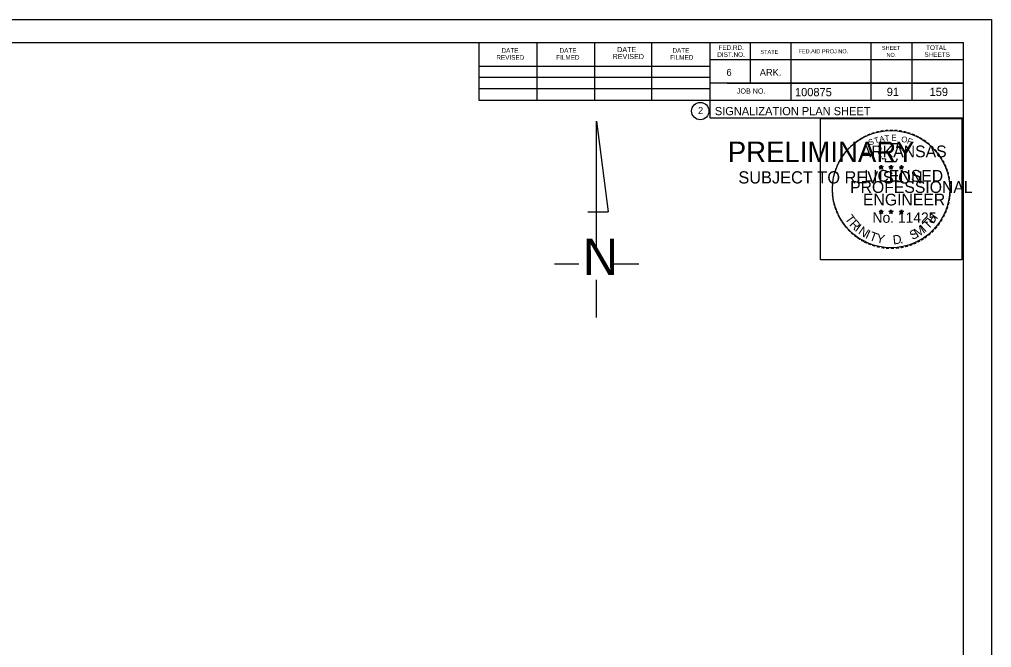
# Model space of a CAD drawing. Extents: x 1709451 to 1710451, y 561684 to 562324.
# Drawn here: x 1709955.8 to 1710451, y 562004 to 562324 of the extents above; entities that cross this region are included whole.
import ezdxf

# ---------------------------------------------------------------- set-up
doc = ezdxf.new("R2010")
doc.units = 0
for name, color, linetype in [('R_Alt Surface', 7, 'Continuous'), ('R_Alt Surface Annot', 7, 'Continuous'), ('R_Axis', 7, 'Continuous'), ('R_Axis Annot', 7, 'Continuous'), ('R_Detour Annot', 7, 'Continuous')]:
    doc.layers.add(name, color=color, linetype=linetype)

msp = doc.modelspace()

# ---------------------------------------------------------------- linework, layer by layer
at = {"layer": 'R_Alt Surface'}
for p, q in [((1709488.22, 562312.31), (1710436.76, 562312.31)), ((1710189.98, 562282.67), (1710189.98, 562312.31)), ((1710307.46, 562312.31), (1710307.46, 562273.91)), ((1710327.98, 562312.31), (1710327.98, 562291.49)), ((1710348.8, 562312.31), (1710348.8, 562282.67)), ((1710389.54, 562312.31), (1710389.54, 562282.67)), ((1710410.36, 562312.31), (1710410.36, 562282.67)), ((1710436.76, 561695.93), (1710436.76, 562312.31)), ((1710219.56, 562282.67), (1710219.56, 562311.71)), ((1710248.84, 562282.67), (1710248.84, 562311.71)), ((1710277.88, 562282.67), (1710277.88, 562311.71)), ((1710436.76, 562303.49), (1710307.46, 562303.49)), ((1710436.76, 562303.55), (1710436.76, 562303.55)), ((1710189.98, 562300.25), (1710307.46, 562300.25)), ((1710189.98, 562294.67), (1710307.46, 562294.67)), ((1710189.98, 562282.67), (1710189.98, 562288.85)), ((1710189.98, 562288.85), (1710307.46, 562288.85)), ((1710436.76, 562291.49), (1710307.46, 562291.49)), ((1710316.34, 562291.49), (1710436.76, 562291.49)), ((1710436.76, 562282.67), (1710189.98, 562282.67)), ((1710307.46, 562273.91), (1710436.76, 562273.91))]:
    msp.add_line(p, q, dxfattribs=at)
msp.add_circle((1710302.62, 562277.32), 4.4, dxfattribs=at)
at = {"layer": 'R_Alt Surface Annot'}
for p, q in [((1709451.02, 562324), (1710451.02, 562324)), ((1710363.59, 562204.86), (1710363.59, 562204.86))]:
    msp.add_line(p, q, dxfattribs=at)
for points in [[(1709451, 562324), (1710451.02, 562324), (1710451.02, 561683.98), (1709451, 561683.98)], [(1710363.83, 562273.55), (1710435.83, 562273.55), (1710435.83, 562201.55), (1710363.83, 562201.55)]]:
    msp.add_lwpolyline(points, close=True, dxfattribs=at)
msp.add_circle((1710399.83, 562237.55), 29.86, dxfattribs=at)
at = {"layer": 'R_Axis Annot'}
for p, q in [((1710393.74, 562249), (1710394.79, 562248.66)), ((1710393.74, 562249), (1710394.5, 562248.86)), ((1710393.74, 562249), (1710394.46, 562248.63)), ((1710394.14, 562247.77), (1710394.79, 562248.66)), ((1710394.14, 562247.77), (1710394.52, 562248.5)), ((1710394.14, 562247.77), (1710394.79, 562248.42)), ((1710394.79, 562249.76), (1710394.67, 562249)), ((1710394.79, 562248.66), (1710394.79, 562249.76)), ((1710394.79, 562249.76), (1710394.94, 562249.01)), ((1710395.83, 562249), (1710394.79, 562248.66)), ((1710395.43, 562247.77), (1710394.79, 562248.66)), ((1710395.43, 562247.77), (1710394.79, 562248.41)), ((1710395.83, 562249), (1710394.97, 562248.85)), ((1710395.43, 562247.77), (1710395.02, 562248.64)), ((1710395.83, 562249), (1710395.22, 562248.69)), ((1710398.75, 562249), (1710399.8, 562248.66)), ((1710398.75, 562249), (1710399.51, 562248.86)), ((1710398.75, 562249), (1710399.47, 562248.63)), ((1710399.15, 562247.77), (1710399.8, 562248.66)), ((1710399.15, 562247.77), (1710399.53, 562248.5)), ((1710399.15, 562247.77), (1710399.8, 562248.42)), ((1710399.8, 562249.76), (1710399.68, 562249)), ((1710399.8, 562248.66), (1710399.8, 562249.76)), ((1710399.8, 562249.76), (1710399.95, 562249.01)), ((1710400.84, 562249), (1710399.8, 562248.66)), ((1710400.44, 562247.77), (1710399.8, 562248.66)), ((1710400.44, 562247.77), (1710399.8, 562248.41)), ((1710400.84, 562249), (1710399.98, 562248.85)), ((1710400.44, 562247.77), (1710400.03, 562248.64)), ((1710400.84, 562249), (1710400.23, 562248.69)), ((1710404.05, 562248.96), (1710405.09, 562248.63)), ((1710404.05, 562248.96), (1710404.81, 562248.82)), ((1710404.05, 562248.96), (1710404.76, 562248.59)), ((1710404.45, 562247.74), (1710405.09, 562248.63)), ((1710404.45, 562247.74), (1710404.82, 562248.47)), ((1710404.45, 562247.74), (1710405.09, 562248.39)), ((1710405.09, 562249.72), (1710404.97, 562248.97)), ((1710405.09, 562248.63), (1710405.09, 562249.72)), ((1710405.09, 562249.72), (1710405.24, 562248.97)), ((1710406.13, 562248.96), (1710405.09, 562248.63)), ((1710405.73, 562247.74), (1710405.09, 562248.63)), ((1710405.73, 562247.74), (1710405.09, 562248.38)), ((1710406.13, 562248.96), (1710405.28, 562248.81)), ((1710405.73, 562247.74), (1710405.32, 562248.61)), ((1710406.13, 562248.96), (1710405.52, 562248.65)), ((1710393.73, 562226.28), (1710394.78, 562225.94)), ((1710393.73, 562226.28), (1710394.49, 562226.14)), ((1710393.73, 562226.28), (1710394.44, 562225.91)), ((1710394.13, 562225.05), (1710394.78, 562225.94)), ((1710394.13, 562225.05), (1710394.51, 562225.78)), ((1710394.13, 562225.05), (1710394.77, 562225.7)), ((1710394.78, 562227.04), (1710394.66, 562226.28)), ((1710395.42, 562225.05), (1710394.77, 562225.69)), ((1710394.78, 562225.94), (1710394.78, 562227.04)), ((1710394.78, 562227.04), (1710394.93, 562226.29)), ((1710395.82, 562226.28), (1710394.78, 562225.94)), ((1710395.42, 562225.05), (1710394.78, 562225.94)), ((1710395.82, 562226.28), (1710394.96, 562226.13)), ((1710395.42, 562225.05), (1710395.01, 562225.93)), ((1710395.82, 562226.28), (1710395.21, 562225.97)), ((1710398.74, 562226.28), (1710399.79, 562225.94)), ((1710398.74, 562226.28), (1710399.5, 562226.14)), ((1710398.74, 562226.28), (1710399.45, 562225.91)), ((1710399.14, 562225.05), (1710399.79, 562225.94)), ((1710399.14, 562225.05), (1710399.52, 562225.78)), ((1710399.14, 562225.05), (1710399.78, 562225.7)), ((1710399.79, 562227.04), (1710399.66, 562226.28)), ((1710400.43, 562225.05), (1710399.78, 562225.69)), ((1710399.79, 562225.94), (1710399.79, 562227.04)), ((1710399.79, 562227.04), (1710399.93, 562226.29)), ((1710400.83, 562226.28), (1710399.79, 562225.94)), ((1710400.43, 562225.05), (1710399.79, 562225.94)), ((1710400.83, 562226.28), (1710399.97, 562226.13)), ((1710400.43, 562225.05), (1710400.01, 562225.93)), ((1710400.83, 562226.28), (1710400.22, 562225.97)), ((1710404.04, 562226.25), (1710405.09, 562225.91)), ((1710404.04, 562226.25), (1710404.8, 562226.11)), ((1710404.04, 562226.25), (1710404.75, 562225.88)), ((1710404.44, 562225.02), (1710405.09, 562225.91)), ((1710404.44, 562225.02), (1710404.82, 562225.75)), ((1710404.44, 562225.02), (1710405.08, 562225.67)), ((1710405.09, 562227.01), (1710404.96, 562226.25)), ((1710405.73, 562225.02), (1710405.08, 562225.66)), ((1710405.09, 562225.91), (1710405.09, 562227.01)), ((1710405.09, 562227.01), (1710405.23, 562226.26)), ((1710406.13, 562226.25), (1710405.09, 562225.91)), ((1710405.73, 562225.02), (1710405.09, 562225.91)), ((1710406.13, 562226.25), (1710405.27, 562226.1)), ((1710405.73, 562225.02), (1710405.32, 562225.9)), ((1710406.13, 562226.25), (1710405.52, 562225.94))]:
    msp.add_line(p, q, dxfattribs=at)
for points in [[(1710393.87, 562260.63), (1710394.67, 562258.15)], [(1710404.4, 562257.86), (1710404.83, 562258.72), (1710402.77, 562258.64), (1710403.22, 562260.63), (1710393.87, 562260.63)], [(1710395.34, 562253.36), (1710395.34, 562253.1), (1710397.03, 562253.04), (1710396.87, 562251.62), (1710402.48, 562251.62), (1710403.08, 562253.23)], [(1710394.79, 562249.76), (1710395.43, 562247.77), (1710393.74, 562249), (1710395.83, 562249), (1710394.14, 562247.77), (1710394.79, 562249.76)], [(1710399.8, 562249.76), (1710400.44, 562247.77), (1710398.75, 562249), (1710400.84, 562249), (1710399.15, 562247.77), (1710399.8, 562249.76)], [(1710405.09, 562249.72), (1710405.73, 562247.74), (1710404.05, 562248.96), (1710406.13, 562248.96), (1710404.45, 562247.74), (1710405.09, 562249.72)], [(1710394.78, 562227.04), (1710395.42, 562225.05), (1710393.73, 562226.28), (1710395.82, 562226.28), (1710394.13, 562225.05), (1710394.78, 562227.04)], [(1710399.79, 562227.04), (1710400.43, 562225.05), (1710398.74, 562226.28), (1710400.83, 562226.28), (1710399.14, 562225.05), (1710399.79, 562227.04)], [(1710405.09, 562227.01), (1710405.73, 562225.02), (1710404.04, 562226.25), (1710406.13, 562226.25), (1710404.44, 562225.02), (1710405.09, 562227.01)]]:
    msp.add_lwpolyline(points, dxfattribs=at)
for centre, radius in [((1710394.79, 562248.66), 0.517), ((1710394.79, 562248.66), 0.434), ((1710394.79, 562248.66), 0.347), ((1710394.79, 562248.66), 0.297), ((1710394.79, 562248.66), 0.224), ((1710394.79, 562248.66), 0.149), ((1710394.79, 562248.66), 0.0889), ((1710399.8, 562248.66), 0.517), ((1710399.8, 562248.66), 0.434), ((1710399.8, 562248.66), 0.347), ((1710399.8, 562248.66), 0.297), ((1710399.8, 562248.66), 0.224), ((1710399.8, 562248.66), 0.149), ((1710399.8, 562248.66), 0.0889), ((1710405.09, 562248.62), 0.517), ((1710405.09, 562248.62), 0.434), ((1710405.09, 562248.62), 0.347), ((1710405.09, 562248.62), 0.297), ((1710405.09, 562248.62), 0.224), ((1710405.09, 562248.62), 0.149), ((1710405.09, 562248.62), 0.0889), ((1710394.78, 562225.94), 0.517), ((1710394.78, 562225.94), 0.434), ((1710394.78, 562225.94), 0.347), ((1710394.78, 562225.94), 0.297), ((1710394.78, 562225.94), 0.224), ((1710394.78, 562225.94), 0.149), ((1710394.78, 562225.94), 0.0889), ((1710399.78, 562225.94), 0.517), ((1710399.78, 562225.94), 0.434), ((1710399.78, 562225.94), 0.347), ((1710399.78, 562225.94), 0.297), ((1710399.78, 562225.94), 0.224), ((1710399.78, 562225.94), 0.149), ((1710399.78, 562225.94), 0.0889), ((1710405.08, 562225.91), 0.517), ((1710405.08, 562225.91), 0.434), ((1710405.08, 562225.91), 0.347), ((1710405.08, 562225.91), 0.297), ((1710405.08, 562225.91), 0.224), ((1710405.08, 562225.91), 0.149), ((1710405.08, 562225.91), 0.0889)]:
    msp.add_circle(centre, radius, dxfattribs=at)
at = {"layer": 'R_Detour Annot'}
for p, q in [((1710249.84, 562272.23), (1710255.62, 562226.03)), ((1710249.84, 562207.15), (1710249.84, 562272.23)), ((1710245.33, 562226.03), (1710255.62, 562226.03)), ((1710228.44, 562199.48), (1710240.78, 562199.48)), ((1710258.06, 562199.48), (1710271.25, 562199.48)), ((1710249.84, 562172.23), (1710249.84, 562191.37))]:
    msp.add_line(p, q, dxfattribs=at)

# ---------------------------------------------------------------- texts
at = {"layer": 'R_Alt Surface'}
for s, height, p in [('DATE', 2.346, (1710201.38, 562307.03)), ('DATE', 2.346, (1710230.96, 562307.03)), ('DATE', 2.638, (1710260.3, 562307.33)), ('DATE', 2.346, (1710288.44, 562307.03)), ('FED.RD.', 2.346, (1710311.9, 562308.47)), ('STATE', 2.052, (1710333.26, 562306.43)), ('FED.AID PROJ.NO.', 2.052, (1710352.64, 562306.73)), ('SHEET', 2.052, (1710395.12, 562308.47)), ('TOTAL', 2.346, (1710417.68, 562308.47)), ('REVISED', 2.346, (1710198.74, 562303.49)), ('FILMED', 2.346, (1710229.22, 562303.49)), ('REVISED', 2.638, (1710257.96, 562303.79)), ('FILMED', 2.346, (1710287.24, 562303.49)), ('DIST.NO.', 2.346, (1710311.3, 562304.93)), ('NO.', 2.052, (1710397.46, 562304.93)), ('SHEETS', 2.346, (1710416.84, 562304.93)), ('6', 3.52, (1710315.98, 562295.27)), ('ARK.', 3.517, (1710332.96, 562295.27)), ('JOB NO.', 2.638, (1710321.26, 562286.21)), ('100875', 4.2, (1710350.89, 562284.89)), ('91', 4.2, (1710397.62, 562284.99)), ('159', 4.2, (1710419.46, 562284.99)), ('2', 3.52, (1710301.47, 562275.86)), ('SIGNALIZATION PLAN SHEET', 4.2, (1710310.05, 562275.2))]:
    msp.add_text(s, height=height, dxfattribs=at).set_placement(p)
at = {"layer": 'R_Axis'}
for s, height, p in [('PRELIMINARY', 10.5, (1710316.62, 562251.3)), ('SUBJECT TO REVISION', 6.2253, (1710322.04, 562240.42))]:
    msp.add_text(s, height=height, dxfattribs=at).set_placement(p)
at = {"layer": 'R_Axis Annot'}
for s, height, rotation, p in [('-', 4.8, 5.8968, (1710396.58, 562265.55)), ('-', 4.8, 0.1862, (1710398.9, 562265.77)), ('-', 4.8, 357.743, (1710401.07, 562265.73)), ('-', 4.8, 36.2317, (1710382.78, 562259.96)), ('-', 4.8, 34.0636, (1710384.52, 562261.14)), ('-', 4.8, 28.7918, (1710386.31, 562262.25)), ('-', 4.8, 24.3072, (1710388.21, 562263.2)), ('S', 3, 21.594, (1710388.93, 562259.66)), ('-', 4.8, 19.1761, (1710390.11, 562264.01)), ('T', 3, 16.4036, (1710391.67, 562260.66)), ('-', 4.8, 13.6302, (1710392.36, 562264.73)), ('A', 3, 11.2132, (1710394.15, 562261.41)), ('-', 4.8, 10.2193, (1710394.39, 562265.22)), ('T', 3, 6.0228, (1710396.7, 562261.91)), ('E', 3, 0.8323, (1710400.01, 562262.24)), ('-', 4.8, 352.1617, (1710403.3, 562265.56)), ('O', 3, 350.4515, (1710404.83, 562261.61)), ('-', 4.8, 347.2049, (1710405.46, 562265.22)), ('F', 3, 340.0707, (1710407.69, 562260.92)), ('-', 4.8, 342.3362, (1710407.36, 562264.75)), ('-', 4.8, 337.8551, (1710409.57, 562264.08)), ('-', 4.8, 334.1211, (1710411.46, 562263.27)), ('-', 4.8, 329.6409, (1710413.2, 562262.42)), ('-', 4.8, 325.8627, (1710415.12, 562261.34)), ('-', 4.8, 48.4231, (1710378.71, 562256.14)), ('-', 4.8, 42.9622, (1710380.06, 562257.57)), ('-', 4.8, 38.9507, (1710381.36, 562258.82)), ('-', 4.8, 320.5297, (1710416.95, 562260.06)), ('-', 4.8, 315.5786, (1710418.75, 562258.6)), ('-', 4.8, 309.8797, (1710420.46, 562256.95)), ('-', 4.8, 58.0706, (1710375.29, 562251.4)), ('-', 4.8, 54.2325, (1710376.27, 562252.98)), ('-', 4.8, 50.6142, (1710377.5, 562254.68)), ('-', 4.8, 306.6522, (1710422.03, 562255.14)), ('-', 4.2, 303.6753, (1710423.49, 562253.44)), ('-', 4.8, 72.3945, (1710372.92, 562245.83)), ('-', 4.8, 67.7743, (1710373.57, 562247.72)), ('-', 4.8, 62.8713, (1710374.35, 562249.56)), ('-', 4.8, 299.6684, (1710424.45, 562251.61)), ('-', 4.8, 294.6628, (1710425.42, 562249.78)), ('-', 4.8, 290.5728, (1710426.19, 562248.05)), ('-', 4.8, 81.2013, (1710371.93, 562241.55)), ('-', 4.8, 75.461, (1710372.33, 562243.69)), ('-', 4.8, 285.1233, (1710426.89, 562246.31)), ('-', 4.8, 280.5493, (1710427.49, 562244.08)), ('-', 4.8, 89.0622, (1710371.63, 562237.38)), ('-', 4.8, 85.1863, (1710371.7, 562239.48)), ('-', 4.8, 276.5962, (1710427.98, 562241.78)), ('-', 4.8, 274.3301, (1710428.16, 562239.61)), ('-', 4.8, 94.1959, (1710371.73, 562235.2)), ('-', 4.8, 98.9479, (1710371.95, 562233.2)), ('-', 4.8, 260.9953, (1710427.99, 562233.76)), ('-', 4.8, 263.5172, (1710428.2, 562235.72)), ('-', 4.8, 269.9407, (1710428.26, 562237.72)), ('-', 4.8, 101.7149, (1710372.35, 562231)), ('-', 4.8, 105.4578, (1710372.84, 562229.22)), ('-', 4.8, 109.0874, (1710373.48, 562227.32)), ('-', 4.8, 252.8681, (1710427.12, 562229.56)), ('-', 4.8, 255.7626, (1710427.66, 562231.72)), ('-', 4.8, 114.0643, (1710374.25, 562225.54)), ('-', 4.8, 115.7289, (1710375.16, 562223.68)), ('T', 4.62, 306.0406, (1710376.06, 562222.46)), ('H', 4.62, 54.6088, (1710421.42, 562219.56)), ('-', 4.8, 244.6197, (1710425.66, 562225.66)), ('-', 4.8, 247.8887, (1710426.45, 562227.54)), ('-', 4.8, 120.4471, (1710376.23, 562221.92)), ('-', 4.8, 125.8934, (1710377.44, 562220.24)), ('-', 4.8, 130.7181, (1710378.83, 562218.58)), ('R', 4.62, 314.005, (1710378.35, 562219.31)), ('I', 4.62, 321.9694, (1710381.05, 562216.52)), ('N', 4.62, 326.5002, (1710382.75, 562215.1)), ('M', 4.62, 32.6563, (1710413.21, 562212.76)), ('I', 4.62, 42.1136, (1710417.06, 562215.3)), ('T', 4.62, 46.6444, (1710418.75, 562216.74)), ('-', 4.8, 231.2538, (1710421.99, 562219.74)), ('-', 4.8, 233.8452, (1710423.28, 562221.44)), ('-', 4.8, 239.0712, (1710424.48, 562223.4)), ('-', 4.8, 134.2238, (1710380.38, 562216.95)), ('-', 4.8, 138.9338, (1710381.95, 562215.56)), ('-', 4.8, 144.6463, (1710383.62, 562214.34)), ('I', 4.62, 335.3603, (1710386.37, 562212.75)), ('T', 4.62, 339.8912, (1710388.36, 562211.76)), ('Y', 4.62, 347.8556, (1710392.01, 562210.43)), ('D', 4.62, 6.3969, (1710400.96, 562209.35)), ('S', 4.62, 26.9312, (1710410.7, 562211.54)), ('-', 4.8, 215.7363, (1710417.34, 562215.11)), ('-', 4.8, 221.0851, (1710418.98, 562216.52)), ('-', 4.8, 225.7653, (1710420.55, 562218.05)), ('-', 4.8, 148.0898, (1710385.3, 562213.23)), ('-', 4.8, 151.5704, (1710387.04, 562212.25)), ('-', 4.8, 154.6002, (1710388.61, 562211.51)), ('-', 4.8, 158.5612, (1710390.48, 562210.75)), ('-', 4.8, 162.7983, (1710392.54, 562210.11)), ('-', 4.8, 167.5555, (1710394.69, 562209.62)), ('.', 4.62, 13.7642, (1710404.54, 562209.73)), ('-', 4.8, 195.4743, (1710408.3, 562210.41)), ('-', 4.8, 200.7184, (1710410.33, 562211.13)), ('-', 4.8, 204.2516, (1710412.19, 562211.95)), ('-', 4.8, 207.3568, (1710414.06, 562212.91)), ('-', 4.8, 212.2491, (1710415.73, 562213.95)), ('-', 4.8, 173.1155, (1710397, 562209.29)), ('-', 4.8, 176.5183, (1710399.25, 562209.13)), ('-', 4.8, 181.5918, (1710401.48, 562209.19)), ('-', 4.8, 185.8167, (1710403.9, 562209.41)), ('-', 4.8, 191.2858, (1710406.11, 562209.81))]:
    msp.add_text(s, height=height, rotation=rotation, dxfattribs=at).set_placement(p)
for s, height, p in [('ARKANSAS', 6, (1710384.43, 562253.77)), ('DWB', 0.03, (1710394.75, 562248.65)), ('DWB', 0.03, (1710399.76, 562248.65)), ('DWB', 0.03, (1710405.05, 562248.61)), ('LICENSED', 6, (1710386.22, 562241.32)), ('PROFESSIONAL', 6, (1710378.95, 562235.61)), ('ENGINEER', 6, (1710385.51, 562229.23)), ('No. 11425', 5.271, (1710390.39, 562220.38)), ('DWB', 0.03, (1710394.74, 562225.93)), ('DWB', 0.03, (1710399.75, 562225.93)), ('DWB', 0.03, (1710405.05, 562225.9))]:
    msp.add_text(s, height=height, dxfattribs=at).set_placement(p)
at = {"layer": 'R_Detour Annot'}
msp.add_text('N', height=18.61, dxfattribs=at).set_placement((1710242.78, 562193.74))

doc.saveas('drawing.dxf')
